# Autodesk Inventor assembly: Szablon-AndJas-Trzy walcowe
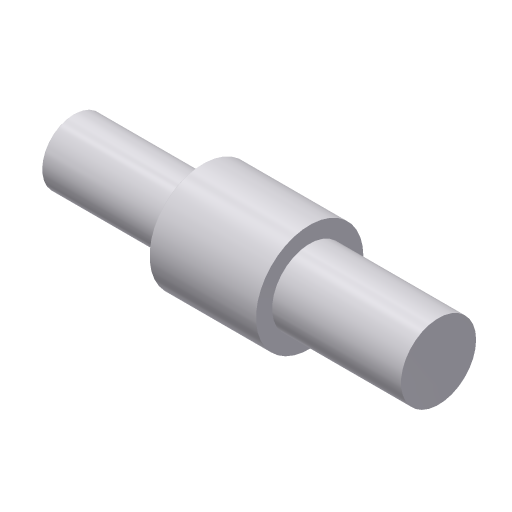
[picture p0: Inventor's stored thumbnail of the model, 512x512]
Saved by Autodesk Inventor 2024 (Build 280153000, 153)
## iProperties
Company: ATC
Created: 2023-03
Part Number: Szablon-AndJas-Trzy walcowe
Document SubType Name: Assembly
Designer: Andrzej Jaskulski
Checked By: A.J.
Engr Approved By: Andrzej Jaskulski
Mfg Approved By: Andrzej Jaskulski
Authority: A.J.
Author: Andrzej Jaskulski
Title: A.J.: Kurs R2024-MEP
Revision Number: 1/24
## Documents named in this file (2)
- C:\Users\AndJas\Documents\R2024-MEP\Obszar roboczy\PZ\Szablon-AndJas-Trzy walcowe.iam
- C:\Users\AndJas\Documents\R2024-MEP\Obszar roboczy\PZ\Szablon-AndJas-Trzy walcowe\Design Accelerator\Szablon-AndJas-Trzy walcowe-WAŁ1.iam
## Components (1 placed, 1 different names)
1. Wał:1 [sub-assembly]
